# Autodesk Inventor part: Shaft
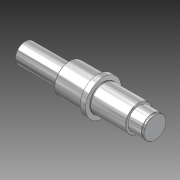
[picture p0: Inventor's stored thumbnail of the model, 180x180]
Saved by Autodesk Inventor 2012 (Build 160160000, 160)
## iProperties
Created: 2007-07
Part Number: Shaft
Material: Steel
Document SubType Name: Modeling
Designer: Designer
Density: 1 g/cm^3
CustomPartVersion: 1
Author: Designer
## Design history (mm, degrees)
sketch "Main Sketch"
  geometry: L1 (0, 0)-(216, 0) reference; L2 (0, 0)-(0, 11); L3 (0, 11)-(50, 11); L4 (50, 11)-(50, 17); L5 (50, 17)-(82, 17); L6 (82, 17)-(82, 20); L7 (88, 20)-(88, 15); L8 (82, 20)-(88, 20); L9 (88, 15)-(93, 15); L10 (198, 15)-(198, 12.5); L11 (93, 15)-(198, 15); L12 (216, 12.5)-(216, 0); L13 (198, 12.5)-(216, 12.5)
  constraints: 26 end point, 6 vertical, 2 horizontal
  dimensions: "d3" = 22 diameter of L3 L1 (derived); "d4" = 34 diameter of L5 L1 (derived); "d5" = 40 diameter of L8 L1 (derived); "d6" = 30 diameter of L9 L1 (derived); "d7" = 30 diameter of L11 L1 (derived); "d8" = 25 diameter of L13 L1 (derived)
revolve "Revolution1" sketch "Main Sketch" stored, may be unused: angle "d9" = 0 deg
chamfer "Chamfer13" distance "d47" = 0.5; stored, may be unused: second distance "d48" = 0.125, angle "d49" = 45 deg
chamfer "Chamfer8" distance "d32" = 0.5; stored, may be unused: second distance "d33" = 0.125, angle "d34" = 45 deg
chamfer "Chamfer10" distance "d38" = 0.5; stored, may be unused: second distance "d39" = 0.125, angle "d40" = 45 deg
chamfer "Chamfer11" distance "d41" = 0.5; stored, may be unused: second distance "d42" = 0.125, angle "d43" = 45 deg
chamfer "Chamfer2" distance "d13" = 2; stored, may be unused: second distance "d14" = 0.125, angle "d15" = 45 deg
fillet "Fillet1" dims "d19" = 2
feature "iFeature4:1"
feature "iFeature27:1"
feature "Shaft Keyway"
body "Solid1"
other parameters: "d0" = 0, "d1" = 0, "d2" = 0
